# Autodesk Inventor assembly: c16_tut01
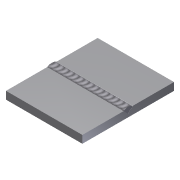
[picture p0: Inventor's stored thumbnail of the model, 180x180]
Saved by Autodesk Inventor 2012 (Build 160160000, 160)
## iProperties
Created: 2010-05
Part Number: c16_tut01
Document SubType Name: Weldment
Designer: CADSoft
Weld Material: Welded Aluminum-6061
Author: CADSoft
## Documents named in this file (2)
- C:\Users\CadCim\Documents\SAILESH\inventor-2011-fact-prt\c16-inv-2011-prt\c16_inv_2012_prt\Tutorials\c16_tut01_inv\c16_tut01.iam
- C:\Users\CadCim\Documents\SAILESH\inventor-2011-fact-prt\c16-inv-2011-prt\Tutorials\c16-tut01-inv-2011\Plate.ipt
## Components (2 placed, 1 different names)
1. Plate:1 — Mate:1, Flush:1, Flush:2
2. Plate:2 — Mate:1, Flush:1, Flush:2
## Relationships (3: Flush 2, Mate 1)
- Mate:1: Plate:1 ↔ Plate:2
- Flush:1: Plate:1 ↔ Plate:2
- Flush:2: Plate:1 ↔ Plate:2
